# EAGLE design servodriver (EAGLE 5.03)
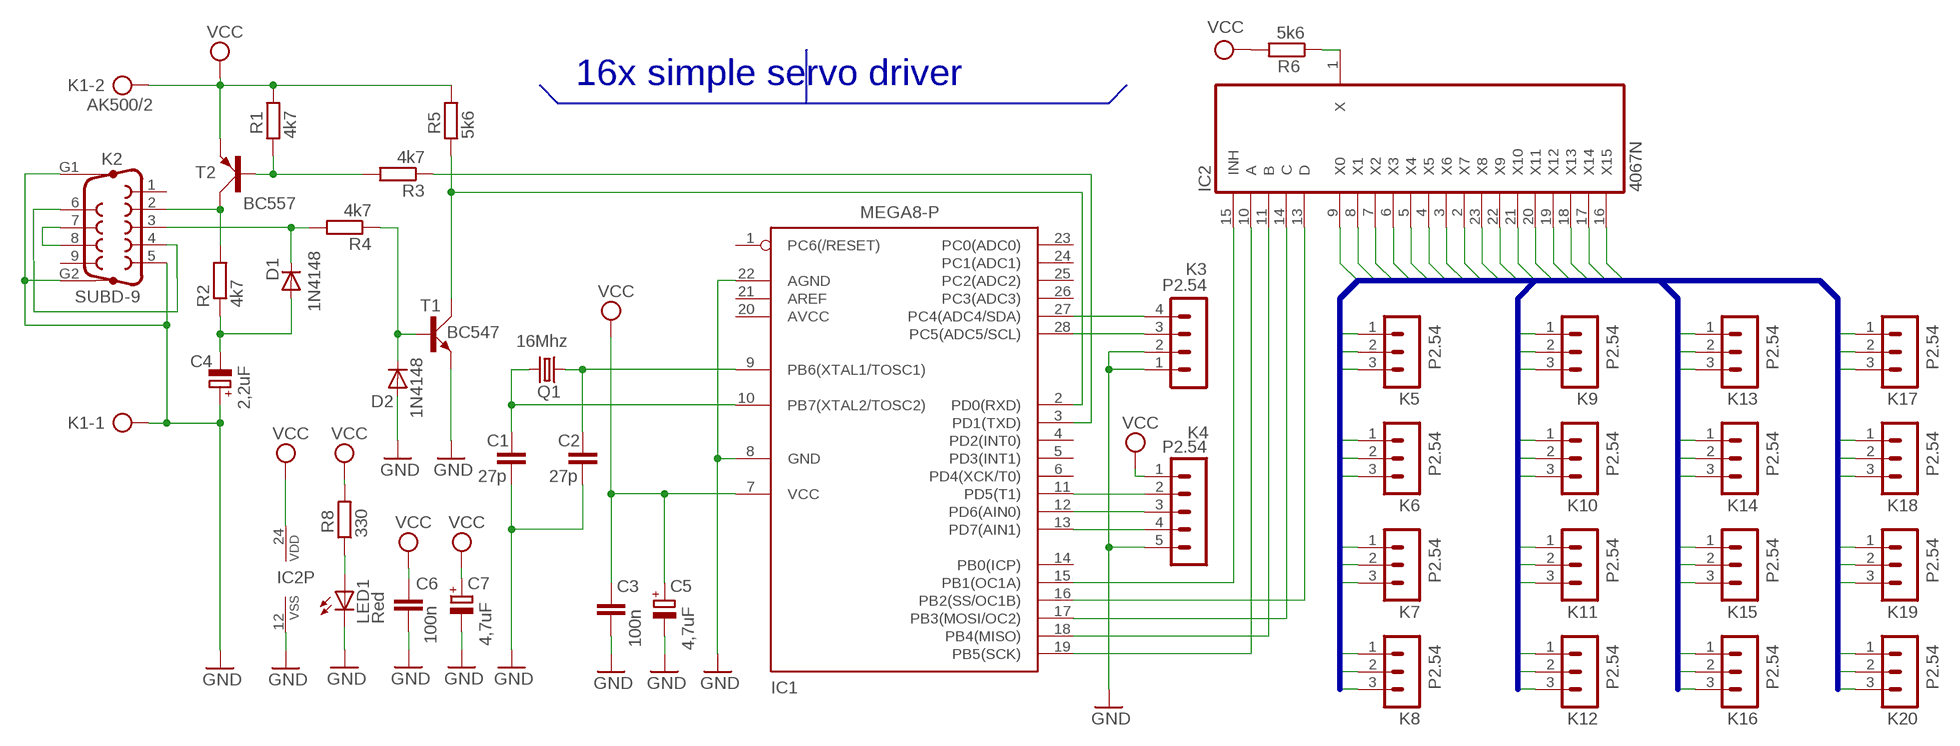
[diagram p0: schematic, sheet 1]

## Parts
C1  27p  C-EU050-024X044  [C050-024X044]
C2  27p  C-EU050-024X044  [C050-024X044]
C3  100n  C-EU050-024X044  [C050-024X044]
C4  2,2uF  CPOL-EUTT2D4  [TT2D4]
C5  4,7uF  CPOL-EUE2.5-5  [E2,5-5]
C6  100n  C-EU050-024X044  [C050-024X044]
C7  4,7uF  CPOL-EUE2.5-5  [E2,5-5]
D1  1N4148  [DO35-10]
D2  1N4148  [DO35-10]
IC1  MEGA8-P  [DIL28-3]
IC2  4067N  [DIL24-6]
K1  AK500/2  [AK500/2]
K2  SUBD-9  F09HP  [F09HP]
K3  P2.54  MA04-1  [MA04-1]
K4  P2.54  MA05-1  [MA05-1]
K5  P2.54  MA03-1  [MA03-1]
K6  P2.54  MA03-1  [MA03-1]
K7  P2.54  MA03-1  [MA03-1]
K8  P2.54  MA03-1  [MA03-1]
K9  P2.54  MA03-1  [MA03-1]
K10  P2.54  MA03-1  [MA03-1]
K11  P2.54  MA03-1  [MA03-1]
K12  P2.54  MA03-1  [MA03-1]
K13  P2.54  MA03-1  [MA03-1]
K14  P2.54  MA03-1  [MA03-1]
K15  P2.54  MA03-1  [MA03-1]
K16  P2.54  MA03-1  [MA03-1]
K17  P2.54  MA03-1  [MA03-1]
K18  P2.54  MA03-1  [MA03-1]
K19  P2.54  MA03-1  [MA03-1]
K20  P2.54  MA03-1  [MA03-1]
LED1  Red  LED5MM  [LED5MM]
Q1  16Mhz  CRYTALHC49U-V  [HC49U-V]
R1  4k7  R-EU_0204/7  [0204/7]
R2  4k7  R-EU_0204/7  [0204/7]
R3  4k7  R-EU_0204/7  [0204/7]
R4  4k7  R-EU_0204/7  [0204/7]
R5  5k6  R-EU_0204/7  [0204/7]
R6  5k6  R-EU_M1206  [M1206]
R8  330  R-EU_0204/7  [0204/7]
T1  BC547  BC547LINE  [TO92-LINE]
T2  BC557  BC557LINE  [TO92-LINE]

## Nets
10: IC2.21(X10) K15.3
GND: C1.2 C2.2 C3.1 C4.+ C5.- C6.1 C7.- D2.A IC1.8(GND) IC1.22(AGND) IC2.12(VSS) K1.1 K2.5 K2.G1 K2.G2 K3.1 K3.2 K4.5 K5.1 K6.1 K7.1 K8.1 K9.1 K10.1 K11.1 K12.1 K13.1 K14.1 K15.1 K16.1 K17.1 K18.1 K19.1 K20.1 LED1.K(C) T1.1(E)
N$1: C2.1 IC1.9(PB6(XTAL1/TOSC1)) Q1.1
N$2: R1.1 R3.2 T2.2(B)
N$3: K2.2 R2.2 T2.3(C)
N$4: IC1.15(PB1(OC1A)) IC2.15(INH)
N$5: C4.- D1.A R2.1
N$6: D2.C R4.1 T1.2(B)
N$7: IC1.2(PD0(RXD)) R5.1 T1.3(C)
N$8: D1.C K2.3 R4.2
N$9: IC1.3(PD1(TXD)) R3.1
N$10: IC1.11(PD5(T1)) K4.2
N$11: C1.1 IC1.10(PB7(XTAL2/TOSC2)) Q1.2
N$12: IC1.27(PC4(ADC4/SDA)) K3.4
N$13: IC1.17(PB3(MOSI/OC2)) IC2.14(C)
N$14: IC1.16(PB2(SS/OC1B)) IC2.13(D)
N$15: IC1.18(PB4(MISO)) IC2.11(B)
N$16: IC1.19(PB5(SCK)) IC2.10(A)
N$17: IC1.28(PC5(ADC5/SCL)) K3.3
N$18: IC1.12(PD6(AIN0)) K4.3
N$19: IC1.13(PD7(AIN1)) K4.4
N$20: IC2.1(X) R6.1
N$24: LED1.A R8.1
N$35: K2.7 K2.8
N$36: K2.4 K2.6
VCC: C3.2 C5.+ C6.2 C7.+ IC1.7(VCC) IC2.24(VDD) K1.2 K4.1 K5.2 K6.2 K7.2 K8.2 K9.2 K10.2 K11.2 K12.2 K13.2 K14.2 K15.2 K16.2 K17.2 K18.2 K19.2 K20.2 R1.2 R5.2 R6.2 R8.2 T2.1(E)
X0: IC2.9(X0) K5.3
X1: IC2.8(X1) K6.3
X2: IC2.7(X2) K7.3
X3: IC2.6(X3) K8.3
X4: IC2.5(X4) K9.3
X5: IC2.4(X5) K10.3
X6: IC2.3(X6) K11.3
X7: IC2.2(X7) K12.3
X8: IC2.23(X8) K13.3
X9: IC2.22(X9) K14.3
X11: IC2.20(X11) K16.3
X12: IC2.19(X12) K17.3
X13: IC2.18(X13) K18.3
X14: IC2.17(X14) K19.3
X15: IC2.16(X15) K20.3
Unconnected: IC1.1(PC6(/RESET)) IC1.4(PD2(INT0)) IC1.5(PD3(INT1)) IC1.6(PD4(XCK/T0)) IC1.14(PB0(ICP)) IC1.20(AVCC) IC1.21(AREF) IC1.23(PC0(ADC0)) IC1.24(PC1(ADC1)) IC1.25(PC2(ADC2)) IC1.26(PC3(ADC3)) K2.1 K2.9

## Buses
B$1:VCC,GND,X0,X1,X2,X3,X4,X5,X6,X7,X8,X9,10,X11,X12,X13,X14,X15
B$1

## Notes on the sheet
- 16x simple servo driver

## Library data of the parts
C1-C3 C6 = rcl:C-EU: CAPACITOR, European symbol
C4 C5 C7 = rcl:CPOL-EU: POLARIZED CAPACITOR, European symbol
D1 D2 = diode:1N4148: DIODE
IC1 = atmel-new:MEGA8-P: MICROCONTROLLER 8 Kbytes FLASH 1 kbytes SRAM 512 bytes EEPROM USART 4-channel 10 bit ADC 2-channel 8 bit ADC
IC2 = 40xx:4067: 16-channel ANALOG MULTIPLEXER
K1 = con-ptr500:AK500/2: CONNECTOR
K2 = con-subd:F09HP: SUB-D
K3 = con-lstb:MA04-1: PIN HEADER
K4 = con-lstb:MA05-1: PIN HEADER
K5-K20 = con-lstb:MA03-1: PIN HEADER
LED1 = led:LED: LED
Q1 = crystal:CRYTAL: CRYSTAL
R1-R6 R8 = rcl:R-EU_: RESISTOR, European symbol
T1 = transistor-small-signal:BC547: NPN TRANSISTOR
T2 = transistor-small-signal:BC557: PNP TRANSISTOR

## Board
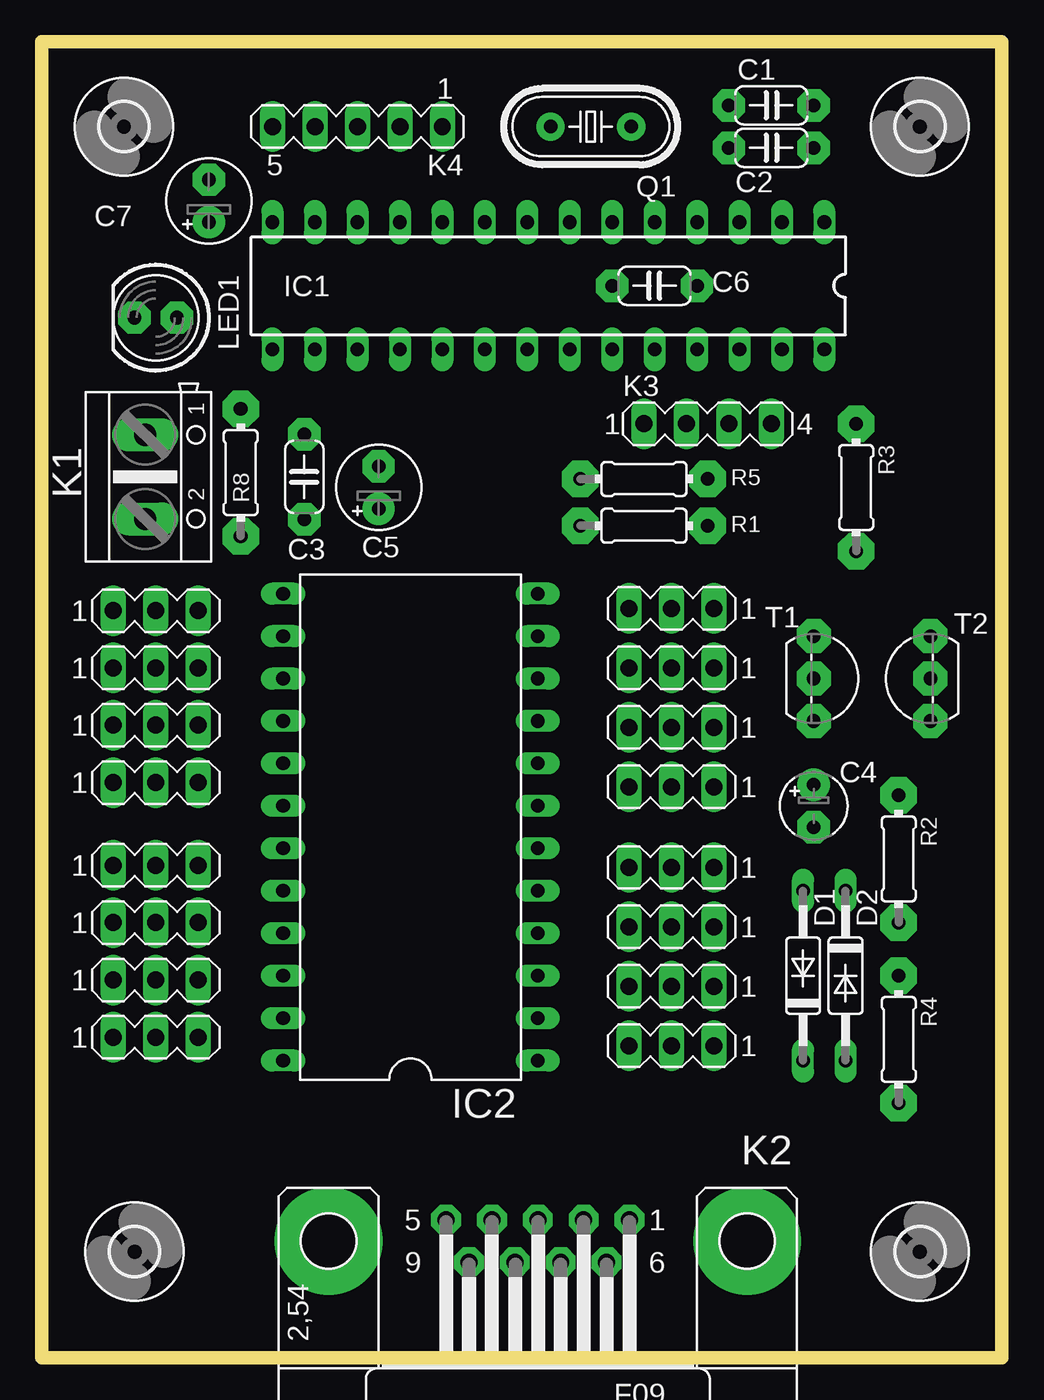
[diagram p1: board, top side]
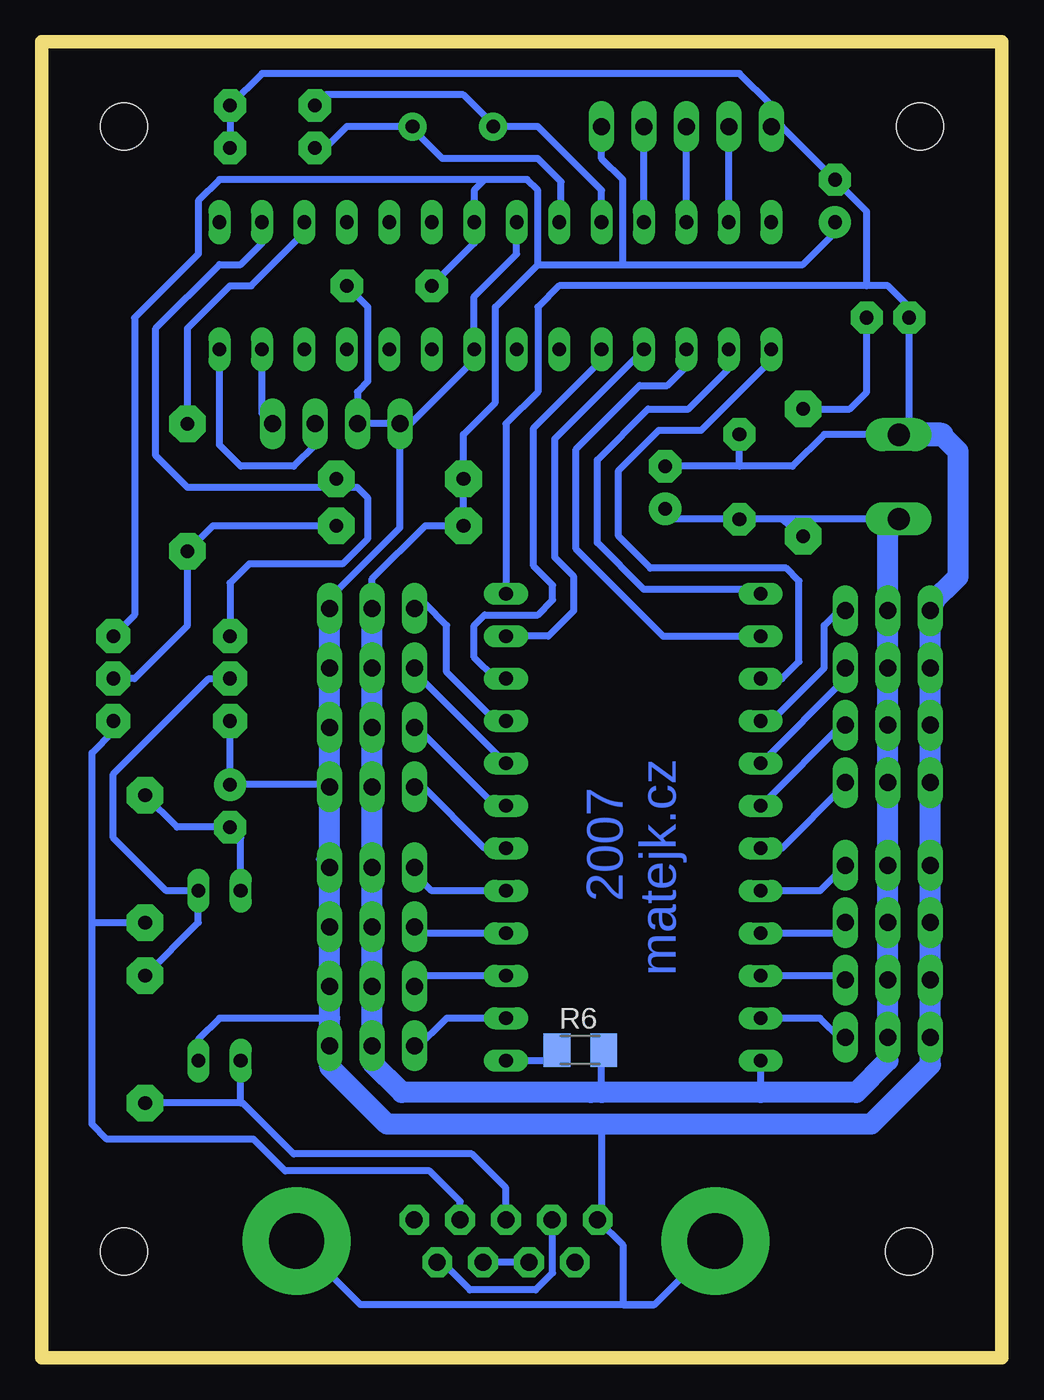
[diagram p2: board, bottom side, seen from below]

Size 57.46 x 78.73 mm. Coordinates in mm from the lower left corner, seen from the top.
Outline: 0,0 57.46,0 57.46,78.73 0,78.73 0,0
Copper layers (1*16): Top 0.035mm / dielectric 1.5mm / Bottom 0.035mm
Design rules "default": minimum track width 1mil, minimum drill 24mil, track to track 8mil, track to pad 8mil, pad to pad 8mil, via to via 8mil, smd to smd 8mil, copper to edge 40mil, drill to drill 8mil, minimum pad ring 10mil, minimum via ring 8mil, stop-mask expansion 4mil, vias tented up to drill 0mil, thermal gap 10mil

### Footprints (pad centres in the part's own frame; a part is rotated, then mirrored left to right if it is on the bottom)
C050-024X044 = drill 0.813 pad 1.93 octagon: 1 -2.54,0; 2 2.54,0
TT2D4 = drill 0.813 pad 1.93 round: + -1.27,0 | drill 0.813 pad 1.93 octagon: - 1.27,0
E2,5-5 = drill 0.813 pad 1.93 round: + -1.27,0 | drill 0.813 pad 1.93 octagon: - 1.27,0
DO35-10 = drill 0.813 long: A 5.08,0; C -5.08,0
DIL28-3 = drill 0.813 long: 1 -16.51,-3.81; 2 -13.97,-3.81; 3 -11.43,-3.81; 4 -8.89,-3.81; 5 -6.35,-3.81; 6 -3.81,-3.81; 7 -1.27,-3.81; 8 1.27,-3.81; 9 3.81,-3.81; 10 6.35,-3.81; 11 8.89,-3.81; 12 11.43,-3.81; 13 13.97,-3.81; 14 16.51,-3.81; 15 16.51,3.81; 16 13.97,3.81; 17 11.43,3.81; 18 8.89,3.81; 19 6.35,3.81; 20 3.81,3.81; 21 1.27,3.81; 22 -1.27,3.81; 23 -3.81,3.81; 24 -6.35,3.81; 25 -8.89,3.81; 26 -11.43,3.81; 27 -13.97,3.81; 28 -16.51,3.81
DIL24-6 = drill 0.813 long: 1 -13.97,-7.62; 2 -11.43,-7.62; 3 -8.89,-7.62; 4 -6.35,-7.62; 5 -3.81,-7.62; 6 -1.27,-7.62; 7 1.27,-7.62; 8 3.81,-7.62; 9 6.35,-7.62; 10 8.89,-7.62; 11 11.43,-7.62; 12 13.97,-7.62; 13 13.97,7.62; 14 11.43,7.62; 15 8.89,7.62; 16 6.35,7.62; 17 3.81,7.62; 18 1.27,7.62; 19 -1.27,7.62; 20 -3.81,7.62; 21 -6.35,7.62; 22 -8.89,7.62; 23 -11.43,7.62; 24 -13.97,7.62
AK500/2 = drill 1.321 long: 1 -2.515,0; 2 2.515,0
F09HP = drill 1.016 pad 1.778 octagon: 1 -5.486,-1.27; 2 -2.743,-1.27; 3 0,-1.27; 4 2.743,-1.27; 5 5.486,-1.27; 6 -4.115,1.27; 7 -1.372,1.27; 8 1.372,1.27; 9 4.115,1.27 | drill 3.302 pad 6.452 round: G1 -12.522,0; G2 12.522,0
MA04-1 = drill 1.016 long: 1 -3.81,0; 2 -1.27,0; 3 1.27,0; 4 3.81,0
MA05-1 = drill 1.016 long: 1 -5.08,0; 2 -2.54,0; 3 0,0; 4 2.54,0; 5 5.08,0
MA03-1 = drill 1.016 long: 1 -2.54,0; 2 0,0; 3 2.54,0
LED5MM = drill 0.813 pad 1.93 octagon: A -1.27,0; K 1.27,0
HC49U-V@1 = drill 0.813 pad 1.676 round: 1 -2.413,0; 2 2.413,0
0204/7 = drill 0.813 pad 2.184 octagon: 1 -3.81,0; 2 3.81,0
M1206 = smd 1.6 x 2: 1 -1.4,0; 2 1.4,0
TO92-LINE = drill 0.813 pad 2.032 octagon: 1 2.54,0; 2 0,0; 3 -2.54,0
2,8 = hole 2.8: 0,0

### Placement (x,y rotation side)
C1  43.65,74.92 0 top
C2  43.65,72.38 0 top
C3  15.71,52.7 270 top
C4  46.19,33.02 270 top
C5  20.15,52.07 90 top
C6  36.67,64.13 180 top
C7  9.99,69.21 90 top
D1  45.55,22.86 90 top
D2  48.1,22.86 270 top
IC1  30.31,64.13 180 top
IC2  22.06,31.75 90 top
K1  6.19,52.7 270 top
K2  29.68,6.98 180 top
K3  39.84,55.88 0 top
K4  18.88,73.66 180 top
K5  37.68,44.83 180 top
K6  37.68,41.27 180 top
K7  37.68,37.71 180 top
K8  37.68,34.16 180 top
K9  37.68,29.33 180 top
K10  37.68,25.78 180 top
K11  37.68,22.22 180 top
K12  37.68,18.66 180 top
K13  6.82,19.17 0 top
K14  6.82,22.6 0 top
K15  6.82,26.03 0 top
K16  6.82,29.46 0 top
K17  6.82,34.41 0 top
K18  6.82,37.84 0 top
K19  6.82,41.27 0 top
K20  6.82,44.7 0 top
LED1  6.82,62.23 180 top
Q1  16Mhz  [HC49U-V@1]  32.86,73.66 180 top
R1  36.03,49.78 180 top
R2  51.27,29.84 270 top
R3  48.73,52.07 270 top
R4  51.27,19.05 270 top
R5  36.03,52.57 180 top
R6  25.23,18.41 0 bottom
R8  11.9,52.95 270 top
T1  46.19,40.63 270 top
T2  53.18,40.63 90 top
U$1  [2,8]  5.55,6.35 0 top
U$2  [2,8]  52.54,6.35 0 top
U$3  [2,8]  52.54,73.66 0 top
U$4  [2,8]  4.92,73.66 0 top

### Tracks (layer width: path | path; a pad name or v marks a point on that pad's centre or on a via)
10
  Bottom 0.406: 9.11,26.16 K15.3 9.99,25.4 IC2.21
GND
  Bottom 0.406: 24.19,13.74 23.96,13.96 23.96,8.48 K2.5 22.7,6.75 22.7,3.17 20.79,3.17 | 4.03,44.7 K20.1 | 4.03,44.7 3.65,45.08 | 4.28,44.45 4.03,44.7 | 6.82,55.24 6.82,55.22 | 6.82,55.24 6.19,55.24 5.55,55.88 LED1.K 5.55,62.86 6.82,64.13 8.09,64.13 | 15.71,53.34 12.54,53.34 10.63,55.24 6.82,55.24 | 40.22,29.84 40.86,29.84 | 40.22,45.72 40.48,45.72 | K5.1 40.09,44.95 40.22,45.46 36.03,49.65 K3.1 | D2.A 48.1,19.05 46.83,20.32 40.22,20.32 | 40.22,33.65 40.22,34.03 40.48,34.29 C4.+ T1.1 | IC2.12 29.68,55.88 27.77,57.78 27.77,62.86 26.5,64.13 8.09,64.13 | K3.1 K3.2 38.57,57.78 37.94,58.41 37.94,62.86 C6.1 | K3.1 35.4,55.88 31.58,59.69 IC1.22 31.58,63.49 29.04,66.03 IC1.8 | K2.G1 38.39,3.17 20.79,3.17 | 20.79,3.17 16.98,6.98 K2.G2 | 15.71,53.34 C3.1 | 8.09,64.13 8.09,68.57 C7.- 13.17,73.66 K4.5 13.8,74.92 15.71,76.83 44.29,76.83 C1.2 C2.2 | 15.71,53.34 C5.-
  Bottom 1.27: 4.28,37.46 K18.1 4.28,38.09 | 4.28,38.09 K19.1 4.28,44.45 | 4.28,38.09 K17.1 K16.1 K15.1 K14.1 K13.1 4.28,17.52 7.84,13.96 23.96,13.96 36.79,13.96 40.22,17.39 K12.1 40.22,20.32 K11.1 K10.1 K9.1 40.22,29.84 40.22,33.65 40.22,34.92 | 40.22,34.92 K7.1 K6.1 K5.1 40.22,45.46 40.22,45.72 | 40.22,34.92 K8.1 | 3.62,55.22 2.63,54.22 2.63,46.73 4.28,45.08 4.28,44.45 | 4.28,44.45 K20.1
  Bottom 1.422: 3.62,55.22 K1.1 6.19,55.24
N$1
  Bottom 0.406: IC1.9 26.38,68.07 26.38,70.35 27.77,71.75 33.49,71.75 35.4,73.66 | 35.4,73.66 Q1.1 | 35.4,73.66 39.21,73.66 40.48,72.38 C2.1
N$2
  Bottom 0.406: T2.2 51.91,40.63 48.73,43.81 R3.2 47.21,49.78 R1.1
N$3
  Bottom 0.406: K2.2 32.42,9.34 34.25,11.17 42.89,11.17 44.79,13.08 53.56,13.08 54.45,13.96 54.45,26.03 | T2.3 53.18,37.46 54.45,36.19 54.45,26.03 | 54.45,26.03 R2.2
N$4
  Bottom 0.406: IC1.15 13.8,59.69 18,55.49 20.54,55.49 22.95,53.08 22.95,49.14 21.04,47.24 12.92,47.24 12.15,46.48 12.15,41.65 13.17,40.63 IC2.15
N$5
  Bottom 0.406: R2.1 49.37,31.75 C4.- 45.55,31.11 D1.A
N$6
  Bottom 0.406: R4.1 48.1,26.03 D2.C 50,27.94 53.18,31.11 53.18,34.92 47.46,40.63 T1.2
N$7
  Bottom 0.406: IC1.2 44.29,66.67 45.55,65.4 46.83,65.4 50.64,61.59 50.64,53.97 48.73,52.07 39.84,52.07 | T1.3 46.19,46.35 45.05,47.49 39.46,47.49 37.94,49.02 37.94,51.43 38.57,52.07 39.84,52.07 | 39.84,52.07 R5.1
N$8
  Bottom 0.406: K2.3 29.68,10.15 31.71,12.19 42.38,12.19 45.43,15.24 45.55,15.24 | 45.55,15.24 R4.2 | 45.55,15.24 D1.C
N$9
  Bottom 0.406: R3.1 48.73,61.59 46.19,64.13 44.92,64.13 41.75,67.3 IC1.3
N$10
  Bottom 0.406: IC1.11 K4.2
N$11
  Bottom 0.406: 30.31,73.66 27.77,73.66 23.96,69.84 IC1.10 | C1.1 40.48,75.56 32.22,75.56 30.31,73.66 | 30.31,73.66 Q1.2
N$12
  Bottom 0.406: IC1.27 44.29,56.51 K3.4
N$13
  Bottom 0.406: IC1.17 18.88,59.3 20.03,58.16 21.68,58.16 25.49,54.35 25.49,48.38 20.28,43.18 IC2.14 14.44,43.43 14.69,43.18
N$14
  Bottom 0.406: IC1.16 16.34,59.18 18.76,56.76 21.17,56.76 24.22,53.72 24.22,48.76 21.43,45.97 14.69,45.97 IC2.13
N$15
  Bottom 0.406: IC2.11 27.14,43.18 25.62,44.7 25.62,46.73 26.76,47.87 26.76,54.99 IC1.18
N$16
  Bottom 0.406: IC2.10 30.31,40.63 31.58,41.91 31.58,43.81 30.95,44.45 27.77,44.45 26.89,45.33 26.89,46.22 28.03,47.37 28.03,55.62 23.96,59.69 IC1.19
N$17
  Bottom 0.406: IC1.28 46.83,54.61 45.55,53.34 42.38,53.34 41.11,54.61 K3.3
N$18
  Bottom 0.406: IC1.12 K4.3
N$19
  Bottom 0.406: IC1.13 K4.4
N$20
  Bottom 0.406: IC2.1 27.77,17.78 27.14,17.78 26.63,18.28 R6.1
N$24
  Bottom 0.406: R8.1 9.11,56.76 8.09,57.78 LED1.A
N$35
  Bottom 0.406: K2.8 K2.7
N$36
  Bottom 0.406: K2.6 33.49,5.71 31.84,4.06 27.9,4.06 26.89,5.07 26.89,8 27.14,8.25 K2.4
VCC
  Bottom 0.406: 27.77,65.4 30.31,62.86 30.31,57.15 32.22,55.24 R5.2 R1.2 | 27.77,65.4 27.77,69.84 28.41,70.48 30.95,70.48 | 30.95,70.48 31.58,69.84 IC1.7 31.58,66.67 C6.2 | T2.1 51.91,44.45 51.91,62.23 48.1,66.03 48.1,69.21 46.83,70.48 30.95,70.48 | 27.77,65.4 22.7,65.4 | 22.7,65.4 22.7,70.48 23.96,71.75 K4.1 | 37.68,45.08 37.43,45.08 K5.2 | K1.2 13.17,50.19 | 13.17,50.19 14.44,50.19 | 13.17,50.19 R8.2 | R1.2 32.22,49.52 | 37.68,45.72 37.68,46.6 34.51,49.78 R1.2 | 14.44,50.19 C3.2 | 22.7,65.4 11.9,65.4 9.99,67.3 C7.+ | 14.44,50.19 19.54,50.19 C5.+ | 14.44,15.87 IC2.24 | 24.6,15.87 23.84,16 | R6.2 23.96,17.65 23.96,15.87
  Bottom 1.27: 6.82,38.09 K18.2 6.82,37.46 | 6.82,37.46 K17.2 K16.2 K15.2 K14.2 K13.2 6.82,17.78 8.72,15.87 14.44,15.87 23.96,15.87 24.6,15.87 35.9,15.87 37.68,17.65 K12.2 K11.2 K10.2 K9.2 K8.2 K7.2 | 6.82,37.46 K19.2 K20.2 6.82,49.52 6.19,50.16 | K7.2 37.68,38.73 | K7.2 K6.2 K5.2 37.68,45.08 37.68,45.72 | 6.19,50.16 5.55,50.16 | 6.19,50.16 K1.2
X0
  Bottom 0.406: 35.14,45.08 35.14,45.72 | IC2.9 30.31,38.09 33.24,41.02 33.24,43.81 34.51,45.08 35.14,45.08 | 35.14,45.08 K5.3
X1
  Bottom 0.406: K6.3 34.76,40.89 34.76,40.63 IC2.8
X2
  Bottom 0.406: IC2.7 30.31,33.02 35.4,38.09 35.4,37.97 K7.3
X3
  Bottom 0.406: IC2.6 30.95,30.48 34.76,34.29 35.27,34.29 | 35.27,34.29 35.4,34.29 | 35.27,34.29 K8.3
X4
  Bottom 0.406: IC2.5 34.12,27.94 35.4,29.21 35.27,29.21 K9.3
X5
  Bottom 0.406: 35.14,26.03 K10.3 34.76,25.4 IC2.4
X6
  Bottom 0.406: K11.3 34.51,22.86 IC2.3
X7
  Bottom 0.406: K12.3 35.14,18.41 33.24,20.32 IC2.2
X8
  Bottom 0.406: K13.3 9.61,19.05 10.88,20.32 IC2.23
X9
  Bottom 0.406: K14.3 9.61,22.6 9.87,22.86 IC2.22
X11
  Bottom 0.406: 9.11,29.71 K16.3 10.88,27.94 IC2.20
X12
  Bottom 0.406: 9.11,34.29 K17.3 9.36,34.29 13.17,30.48 IC2.19
X13
  Bottom 0.406: 9.61,37.84 K18.3 9.36,38.09 IC2.18
X14
  Bottom 0.406: K19.3 9.23,41.27 | 9.11,41.4 K19.3 | IC2.17 9.36,40.63 K19.3
X15
  Bottom 0.406: 9.11,44.45 K20.3 9.36,45.08 10.63,43.81 10.63,41.27 13.8,38.09 IC2.16

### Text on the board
Bottom: 2007 | matejk.cz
